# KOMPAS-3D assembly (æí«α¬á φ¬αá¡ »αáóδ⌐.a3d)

Referenced files in D:\МОДЕЛЬ ТАНКА Т90\ДЕТАЛИ\КОРПУС\МЕТАЛЛ\КОРПУС ШТАМПОВКА\: экран правый.m3d
Referenced files in D:\МОДЕЛЬ ТАНКА Т90\ДЕТАЛИ\ОБЩИЕ ДЕТАЛИ\: шарнир экрана большой.m3d, шарниры ящиков.m3d
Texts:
  Сборка экран правый
  stalker61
